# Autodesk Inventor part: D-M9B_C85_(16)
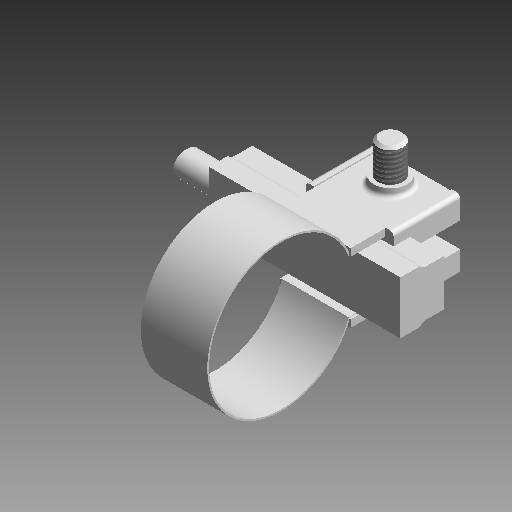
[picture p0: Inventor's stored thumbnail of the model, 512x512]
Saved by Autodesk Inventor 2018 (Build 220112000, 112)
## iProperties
Category: PARTsolutions
Company: SMC
Part Number: D-M9B_C85_(16)
Material: Generic
Catalog Web Link: www.cadenas.de
Description: C85/CD85 SW-ISO Standard Air Cylinder:Standard Type Double Acting Single Rod
Vendor: SMC
Document SubType Name: Modeling
Designer: partserver
Manufacturer: SMC
Mass: 1.40986 g
Surface Area: 22.9985 cm^2
Volume: 1.40986 cm^3
Density: 1 g/cm^3
Appearance: PSOLRGB-255-255-255
PSOL_IDENT_0: {$CADENAS_DATA\23d-libs\smc_jp\actuator\standard_air_cylinder\c85\c85\parts\c85_sw_band.prj},174 {VT
PSOL_IDENT_1: YP=3D},{NB=D-M9B_C85_(16)},{LINA=D-M9B_C85},{NN=C85/CD85 SW},{DATE=09.12.2020 02:57:06},{GEOMDATE=03
PSOL_IDENT_2: .08.2017 08:12:00},{VERSION=},{LINEID=40},{WBVAR=AUTOSW},{WBNUMERIC=}  {NB=D-M9B_C85_(16)},{LINA=D-M
PSOL_IDENT_3: 9B_C85},{KT=DUMMY},{BORE=16.000},{AUTOSW=-M9B},{ASN=A},{SWITCHS=F},{HS=11.1},{ORDER=D-M9B_C85},{D1=1
PSOL_IDENT_4: 7.400}
NB: D-M9B_C85_(16)
NN: C85/CD85 SW
NT: ISO Standard Air Cylinder:Standard Type Double Acting Single Rod
NBSYN: $ORDER._($BORE.)
LINA: D-M9B_C85
CATALOG: SMC (JP
BORE: 16
AUTOSW: M9B
D1: 17.4
SUPPLIER: SMC
ARTICLENO: D-M9B_C85_(16)
BOMINFO: D-M9B_C85
CREATOR: CADENAS GmbH
Title: D-M9B_C85
Author: Cadenas PARTsolutions
Comments: ISO Standard Air Cylinder:Standard Type Double Acting Single Rod
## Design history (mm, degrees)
sketch "Sketch_14"
  geometry: L1 (3, 1.5)-(6, 1.5); L2 (6.5, 1)-(6.5, -1); L3 (6, -1.5)-(3, -1.5); L4 (3, -1.5)-(3, -3.75); L5 (3.5, -4.25)-(4, -4.25); L6 (4, -4.25)-(4, -3.25); L7 (4, -3.25)-(12.6, -3.25); L8 (12.6, -3.25)-(12.6, -4.25); L9 (12.6, -4.25)-(13.1, -4.25); L10 (13.6, -3.75)-(13.6, -1.5); L11 (13.6, -1.5)-(10.6, -1.5); L12 (10.1, -1)-(10.1, 1); L13 (10.6, 1.5)-(13.6, 1.5); L14 (13.6, 1.5)-(13.6, 3.75); L15 (13.1, 4.25)-(12.6, 4.25); L16 (12.6, 4.25)-(12.6, 3.25); L17 (12.6, 3.25)-(4, 3.25); L18 (4, 3.25)-(4, 4.25); L19 (4, 4.25)-(3.5, 4.25); L20 (3, 3.75)-(3, 1.5); A1 r 0.5 centre (6, 1) between (6.5, 1) and (6, 1.5); A2 r 0.5 centre (6, -1) between (6, -1.5) and (6.5, -1); A3 r 0.5 centre (3.5, -3.75) between (3, -3.75) and (3.5, -4.25); A4 r 0.5 centre (13.1, -3.75) between (13.1, -4.25) and (13.6, -3.75); A5 r 0.5 centre (10.6, -1) between (10.1, -1) and (10.6, -1.5); A6 r 0.5 centre (10.6, 1) between (10.6, 1.5) and (10.1, 1); A7 r 0.5 centre (13.1, 3.75) between (13.6, 3.75) and (13.1, 4.25); A8 r 0.5 centre (3.5, 3.75) between (3.5, 4.25) and (3, 3.75)
  constraints: 40 end point, 16 point on circle, 8 centre point
extrude "Extrusion1" join sketch "Sketch_14" distance "d0" = 8; taper "d1" = 0 deg
sketch "Sketch_13"
  geometry: L1 (1.4, 2.8)-(1.4, -2.8); L2 (1.4, -2.8)-(2.9, -2.8); L3 (2.9, -2.8)-(2.9, -1.7); L4 (2.9, -1.7)-(3.4, -1.7); L5 (3.4, -1.7)-(3.4, 1.7); L6 (3.4, 1.7)-(2.9, 1.7); L7 (2.9, 1.7)-(2.9, 2.8); L8 (2.9, 2.8)-(1.4, 2.8)
  constraints: 16 end point
extrude "Extrusion2" cut sketch "Sketch_13" distance "d2" = 20; taper "d3" = 0 deg
sketch "Sketch_12"
  geometry: L1 (-3.175, -2.3)-(3.175, -2.3); L2 (3.175, -2.3)-(3.175, -0.01); L3 (2.775, 0.79)-(2.775, 2.9); L4 (2.775, 2.9)-(-2.775, 2.9); L5 (-2.775, 2.9)-(-2.775, 0.79); L6 (-3.175, -0.01)-(-3.175, -2.3); A1 r 1 centre (3.775, 0.79) between (2.775, 0.79) and (3.175, -0.01); A2 r 1 centre (-3.775, 0.79) between (-3.175, -0.01) and (-2.775, 0.79)
  constraints: 12 end point, 4 point on circle, 2 centre point
extrude "Extrusion3" join sketch "Sketch_12" distance "d4" = 23; taper "d5" = 0 deg
sketch "Sketch_8"
  geometry: L1 (1.323, -1.5)-(3.1, -1.5); L2 (3.1, -1.5)-(3.1, 1.5); L3 (3.1, 1.5)-(1.323, 1.5); A1 r 2 centre (0, 0) between (1.323, 1.5) and (1.323, -1.5)
  constraints: 6 end point, 2 point on circle, 1 centre point
extrude "Extrusion4" cut sketch "Sketch_8" distance "d6" = 22; taper "d7" = 0 deg
sketch "Sketch_19"
  geometry: L1 (1.428, -1.4)-(2.6, -1.4); L2 (2.6, -1.4)-(2.6, 1.4); L3 (2.6, 1.4)-(1.428, 1.4); A1 r 2 centre (0, 0) between (1.428, 1.4) and (1.428, -1.4)
  constraints: 6 end point, 2 point on circle, 1 centre point
extrude "Extrusion5" join sketch "Sketch_19" distance "d8" = 22; taper "d9" = 0 deg
sketch "Sketch_5"
  geometry: C1 r 1.2 at (2, 0); C2 r 1 at (2, 0); 2 further points
  constraints: 2 centre point
extrude "Extrusion6" cut sketch "Sketch_5" stored distance "d10" = 2; taper "d11" = 0 deg
sketch "Sketch_6"
  geometry: L1 (1.492, -0.861)-(2.861, 0.508); L2 (2.508, 0.861)-(1.139, -0.508); A1 r 1 centre (2, 0) between (1.139, -0.508) and (1.492, -0.861); A2 r 1 centre (2, 0) between (2.861, 0.508) and (2.508, 0.861)
  constraints: 4 end point, 4 point on circle, 2 centre point
extrude "Extrusion7" cut sketch "Sketch_6" stored distance "d12" = 1; taper "d13" = 0 deg
sketch "Sketch_26"
  geometry: L1 (8.15, 0.5)-(8.15, -0.5); L2 (8.4, -0.75)-(10.6, -0.75); L3 (10.85, -0.5)-(10.85, 0.5); L4 (10.6, 0.75)-(8.4, 0.75); A1 r 0.25 centre (8.4, -0.5) between (8.15, -0.5) and (8.4, -0.75); A2 r 0.25 centre (10.6, -0.5) between (10.6, -0.75) and (10.85, -0.5); A3 r 0.25 centre (10.6, 0.5) between (10.85, 0.5) and (10.6, 0.75); A4 r 0.25 centre (8.4, 0.5) between (8.4, 0.75) and (8.15, 0.5)
  constraints: 8 end point, 8 point on circle, 4 centre point
extrude "Extrusion8" cut sketch "Sketch_26" stored distance "d14" = 0.2; taper "d15" = 0 deg
sketch "Sketch_21"
  geometry: L1 (0.25, 1.35)-(-0.25, 1.35); L2 (-0.25, -1.35)-(0.25, -1.35); A1 r 1.35 centre (-0.25, 0) between (-0.25, 1.35) and (-0.25, -1.35); A2 r 1.35 centre (0.25, 0) between (0.25, -1.35) and (0.25, 1.35)
  constraints: 4 end point, 4 point on circle, 2 centre point
extrude "Extrusion9" join sketch "Sketch_21" distance "d16" = 27; taper "d17" = 0 deg
sketch "Sketch_7"
  geometry: L1 (3.45, -3.096)-(3.45, 8.8); L2 (3.45, 8.8)-(3.25, 8.8); L3 (3.25, 8.8)-(3.25, -3.23); L4 (-3.175, -3.2)-(-3.175, 8.8); L5 (-3.175, 8.8)-(-3.375, 8.8); L6 (-3.375, 8.8)-(-3.375, -3.065); A1 r 8.9 centre (0, -11.3) between (-3.375, -3.065) and (3.45, -3.096); A2 r 8.7 centre (0, -11.3) between (-3.175, -3.2) and (3.25, -3.23)
  constraints: 12 end point, 4 point on circle, 2 centre point
extrude "Extrusion10" join sketch "Sketch_7" stored distance "d18" = 8; taper "d19" = 0 deg
sketch "Sketch_15"
  geometry: L1 (3.25, 8.8)-(3.25, -3.23); L2 (3.25, -3.23)-(4.15, -3.23); L3 (4.15, -3.23)-(4.15, 8.8); L4 (4.15, 8.8)-(3.25, 8.8)
  constraints: 8 end point
extrude "Extrusion11" join sketch "Sketch_15" stored distance "d20" = 8.5; taper "d21" = 0 deg
sketch "Sketch_16"
  geometry: L1 (-4.15, 8.8)-(-4.15, -3.23); L2 (-4.15, -3.23)-(-3.25, -3.23); L3 (-3.25, -3.23)-(-3.25, 8.8); L4 (-3.25, 8.8)-(-4.15, 8.8)
  constraints: 8 end point
extrude "Extrusion12" join sketch "Sketch_16" stored distance "d22" = 8.5; taper "d23" = 0 deg
sketch "Sketch_17"
  geometry: L1 (9.05, 5.8)-(-7.45, 5.8); L2 (-7.45, 5.8)-(-7.45, 6.55); L3 (-5.45, 8.55)-(-4.15, 8.55); L4 (-4.15, 8.55)-(-4.15, 7.3); L5 (-4.15, 7.3)-(4.15, 7.3); L6 (4.15, 7.3)-(4.15, 8.3); L7 (4.65, 7.8)-(5.15, 7.8); L8 (5.15, 7.8)-(5.15, 7.3); L9 (5.15, 7.3)-(8.743, 7.3); L10 (8.743, 7.3)-(9.05, 6.994); L11 (9.05, 6.994)-(9.05, 5.8); L12 (9.05, 5.8)-(-7.45, 5.8); A1 r 2 centre (-5.45, 6.55) between (-5.45, 8.55) and (-7.45, 6.55); A2 r 0.5 centre (4.65, 8.3) between (4.15, 8.3) and (4.65, 7.8)
  constraints: 24 end point, 4 point on circle, 2 centre point
revolve "Revolution1" sketch "Sketch_17" stored, may be unused: angle "d24" = 360 deg
thread "Thread1" dims "d25" = 3.5935, "d26" = 0
sketch "Sketch_18"
  geometry: L1 (-2, 0.343)-(-2, -0.343); L2 (-2, -0.343)-(-1.342, -0.343); L3 (-0.343, -1.342)-(-0.343, -2); L4 (-0.343, -2)-(0.343, -2); L5 (0.343, -2)-(0.343, -1.342); L6 (1.342, -0.343)-(2, -0.343); L7 (2, -0.343)-(2, 0.343); L8 (2, 0.343)-(1.342, 0.343); L9 (0.343, 1.342)-(0.343, 2); L10 (0.343, 2)-(-0.343, 2); L11 (-0.343, 2)-(-0.343, 1.342); L12 (-1.342, 0.343)-(-2, 0.343); A1 r 1 centre (-1.343, -1.343) between (-0.343, -1.342) and (-1.342, -0.343); A2 r 1 centre (1.343, -1.343) between (1.342, -0.343) and (0.343, -1.342); A3 r 1 centre (1.343, 1.343) between (0.343, 1.342) and (1.342, 0.343); A4 r 1 centre (-1.343, 1.343) between (-1.342, 0.343) and (-0.343, 1.342)
  constraints: 24 end point, 8 point on circle, 4 centre point
extrude "Extrusion13" cut sketch "Sketch_18" distance "d27" = 1.5; taper "d28" = 0 deg
node "SW_XY"
node "SW_YZ"
node "SW_ZX"
node "SW_X"
node "SW_Y"
node "SW_Z"
node "SW_Center"
body "Solid1"
